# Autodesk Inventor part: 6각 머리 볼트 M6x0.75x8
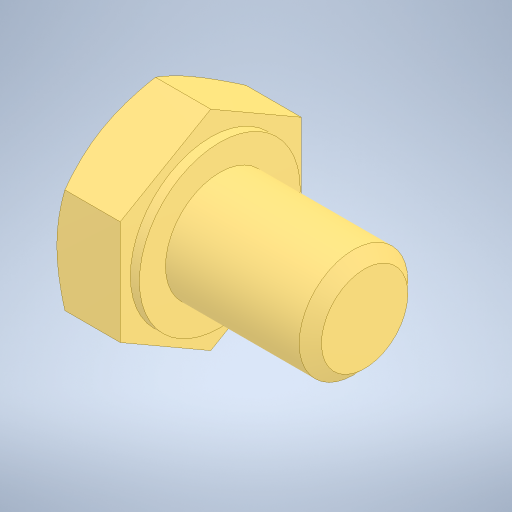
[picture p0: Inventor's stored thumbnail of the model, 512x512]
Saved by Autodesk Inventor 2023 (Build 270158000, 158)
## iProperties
Created: 2025-10
Part Number: 6각 머리 볼트 M6x0.75x8
Material: 강철, 연강
Description: 6각 머리 볼트 및 6각 머리 나사
Document SubType Name: Modeling
Designer: home
Density: 7.85 g/cm^3
Appearance: 기본값
Author: jhkim
Sending System: Autodesk Inventor 2026
Preprocessor: ST-DEVELOPER v20.1
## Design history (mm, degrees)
sketch "스케치1"
  geometry: 1 further point
  constraints: 1 other
feature "Solid1"
node "솔리드1"
